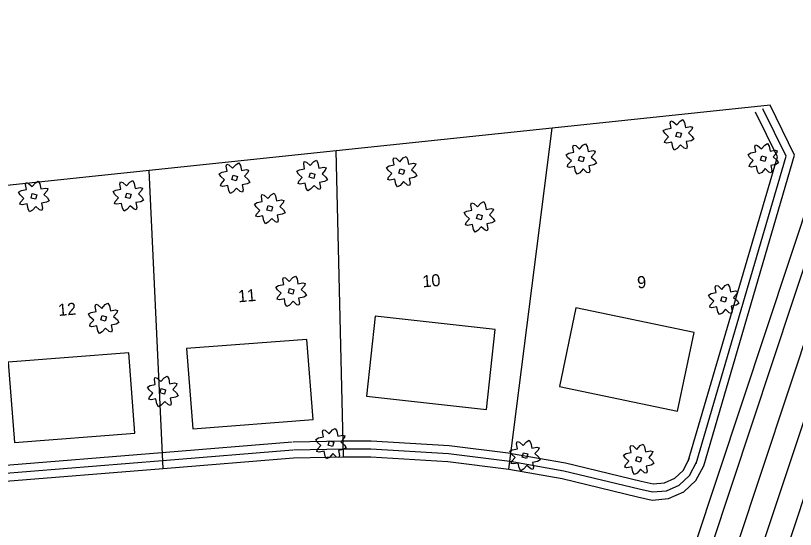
# Model space of a CAD drawing. Extents: x 1810019 to 1811399, y 1074962 to 1076105.
# Drawn here: x 1810548 to 1810935.4, y 1075849.4 to 1076104.6 of the extents above; entities that cross this region are included whole.
import ezdxf

# ---------------------------------------------------------------- set-up
doc = ezdxf.new("R2010")
doc.units = 0
for name, color, linetype in [('Environmental-New trees', 7, 'Continuous'), ('Property-Buildings', 7, 'Continuous'), ('Roadway-Centerline main', 7, 'Continuous'), ('Roadway-Edge of pavement', 7, 'Continuous'), ('Roadway-Edge of shoulder', 7, 'Continuous'), ('Roadway-Land lines', 7, 'Continuous'), ('Roadway-Sidewalks', 7, 'Continuous'), ('Text-Property owner', 7, 'Continuous')]:
    doc.layers.add(name, color=color, linetype=linetype)

msp = doc.modelspace()

# ---------------------------------------------------------------- linework, layer by layer
at = {"layer": 'Environmental-New trees'}
for points in [[(1810870.43, 1076041.5), (1810870.74, 1076042.58), (1810872.43, 1076044.44), (1810870.57, 1076046.14), (1810869.79, 1076047.52), (1810871.14, 1076048.28), (1810873.65, 1076048.77), (1810873.18, 1076051.25), (1810873.48, 1076052.33), (1810874.57, 1076052.02), (1810876.43, 1076050.33), (1810878.12, 1076052.19), (1810879.51, 1076052.97), (1810880.29, 1076051.58), (1810880.76, 1076049.11), (1810883.23, 1076049.58), (1810884.31, 1076049.28), (1810883.94, 1076048.12), (1810882.31, 1076046.33), (1810884.18, 1076044.64), (1810884.95, 1076043.25), (1810883.6, 1076042.49), (1810881.09, 1076042), (1810881.57, 1076039.53), (1810881.26, 1076038.45), (1810880.18, 1076038.75), (1810878.32, 1076040.45), (1810876.62, 1076038.58), (1810875.24, 1076037.81), (1810874.46, 1076039.19), (1810873.99, 1076041.67), (1810871.51, 1076041.19)], [(1810876.59, 1076046.78), (1810878.76, 1076046.17), (1810878.15, 1076044), (1810875.98, 1076044.61)], [(1810822.11, 1076029.49), (1810822.41, 1076030.58), (1810824.1, 1076032.44), (1810822.24, 1076034.13), (1810821.47, 1076035.52), (1810822.82, 1076036.28), (1810825.32, 1076036.77), (1810824.85, 1076039.24), (1810825.16, 1076040.32), (1810826.24, 1076040.02), (1810828.1, 1076038.32), (1810829.79, 1076040.19), (1810831.18, 1076040.96), (1810831.96, 1076039.58), (1810832.43, 1076037.1), (1810834.91, 1076037.58), (1810835.99, 1076037.27), (1810835.62, 1076036.12), (1810833.99, 1076034.33), (1810835.85, 1076032.63), (1810836.63, 1076031.25), (1810835.28, 1076030.49), (1810832.77, 1076029.99), (1810833.24, 1076027.52), (1810832.94, 1076026.44), (1810831.85, 1076026.75), (1810829.99, 1076028.44), (1810828.3, 1076026.58), (1810826.91, 1076025.8), (1810826.13, 1076027.19), (1810825.66, 1076029.66), (1810823.19, 1076029.19)], [(1810912.52, 1076029.64), (1810912.82, 1076030.72), (1810914.51, 1076032.59), (1810912.65, 1076034.28), (1810911.88, 1076035.67), (1810913.23, 1076036.42), (1810915.74, 1076036.92), (1810915.26, 1076039.39), (1810915.57, 1076040.47), (1810916.65, 1076040.17), (1810918.51, 1076038.47), (1810920.21, 1076040.33), (1810921.59, 1076041.11), (1810922.37, 1076039.72), (1810922.84, 1076037.25), (1810925.32, 1076037.73), (1810926.4, 1076037.42), (1810926.03, 1076036.26), (1810924.4, 1076034.48), (1810926.26, 1076032.78), (1810927.04, 1076031.4), (1810925.69, 1076030.64), (1810923.18, 1076030.14), (1810923.65, 1076027.67), (1810923.35, 1076026.59), (1810922.26, 1076026.9), (1810920.4, 1076028.59), (1810918.71, 1076026.73), (1810917.32, 1076025.95), (1810916.54, 1076027.34), (1810916.07, 1076029.81), (1810913.6, 1076029.34)], [(1810688.34, 1076021.25), (1810688.65, 1076022.34), (1810690.34, 1076024.2), (1810688.48, 1076025.89), (1810687.7, 1076027.28), (1810689.05, 1076028.04), (1810691.56, 1076028.53), (1810691.09, 1076031), (1810691.39, 1076032.08), (1810692.48, 1076031.78), (1810694.34, 1076030.09), (1810696.03, 1076031.95), (1810697.42, 1076032.73), (1810698.2, 1076031.34), (1810698.67, 1076028.87), (1810701.14, 1076029.34), (1810702.22, 1076029.03), (1810701.85, 1076027.88), (1810700.22, 1076026.09), (1810702.09, 1076024.4), (1810702.86, 1076023.01), (1810701.51, 1076022.25), (1810699, 1076021.76), (1810699.48, 1076019.29), (1810699.17, 1076018.2), (1810698.09, 1076018.51), (1810696.23, 1076020.2), (1810694.53, 1076018.34), (1810693.15, 1076017.56), (1810692.37, 1076018.95), (1810691.89, 1076021.42), (1810689.42, 1076020.95)], [(1810732.87, 1076023.21), (1810733.17, 1076024.29), (1810734.87, 1076026.16), (1810733.01, 1076027.85), (1810732.23, 1076029.24), (1810733.58, 1076029.99), (1810736.09, 1076030.49), (1810735.61, 1076032.96), (1810735.92, 1076034.04), (1810737, 1076033.74), (1810738.86, 1076032.04), (1810740.56, 1076033.9), (1810741.95, 1076034.68), (1810742.72, 1076033.29), (1810743.2, 1076030.82), (1810745.67, 1076031.3), (1810746.75, 1076030.99), (1810746.38, 1076029.83), (1810744.75, 1076028.05), (1810746.61, 1076026.35), (1810747.39, 1076024.97), (1810746.04, 1076024.21), (1810743.53, 1076023.71), (1810744, 1076021.24), (1810743.7, 1076020.16), (1810742.62, 1076020.46), (1810740.75, 1076022.16), (1810739.06, 1076020.3), (1810737.67, 1076019.52), (1810736.9, 1076020.91), (1810736.42, 1076023.38), (1810733.95, 1076022.91)], [(1810828.27, 1076034.77), (1810830.44, 1076034.16), (1810829.83, 1076031.99), (1810827.66, 1076032.6)], [(1810918.68, 1076034.92), (1810920.85, 1076034.31), (1810920.24, 1076032.14), (1810918.07, 1076032.75)], [(1810649.82, 1076020.02), (1810650.12, 1076021.1), (1810651.82, 1076022.97), (1810649.95, 1076024.66), (1810649.18, 1076026.05), (1810650.53, 1076026.81), (1810653.04, 1076027.3), (1810652.56, 1076029.77), (1810652.87, 1076030.85), (1810653.95, 1076030.55), (1810655.81, 1076028.85), (1810657.51, 1076030.72), (1810658.89, 1076031.49), (1810659.67, 1076030.1), (1810660.14, 1076027.63), (1810662.62, 1076028.11), (1810663.7, 1076027.8), (1810663.33, 1076026.65), (1810661.7, 1076024.86), (1810663.56, 1076023.16), (1810664.34, 1076021.78), (1810662.99, 1076021.02), (1810660.48, 1076020.52), (1810660.95, 1076018.05), (1810660.65, 1076016.97), (1810659.56, 1076017.28), (1810657.7, 1076018.97), (1810656.01, 1076017.11), (1810654.62, 1076016.33), (1810653.84, 1076017.72), (1810653.37, 1076020.19), (1810650.9, 1076019.72)], [(1810655.98, 1076025.3), (1810658.15, 1076024.69), (1810657.54, 1076022.52), (1810655.37, 1076023.13)], [(1810694.5, 1076026.53), (1810696.67, 1076025.92), (1810696.06, 1076023.76), (1810693.89, 1076024.37)], [(1810739.03, 1076028.49), (1810741.2, 1076027.88), (1810740.59, 1076025.71), (1810738.42, 1076026.32)], [(1810550.11, 1076010.89), (1810550.42, 1076011.97), (1810552.11, 1076013.83), (1810550.25, 1076015.53), (1810549.47, 1076016.92), (1810550.82, 1076017.67), (1810553.33, 1076018.17), (1810552.86, 1076020.64), (1810553.16, 1076021.72), (1810554.24, 1076021.42), (1810556.11, 1076019.72), (1810557.8, 1076021.58), (1810559.19, 1076022.36), (1810559.97, 1076020.97), (1810560.44, 1076018.5), (1810562.91, 1076018.97), (1810563.99, 1076018.67), (1810563.62, 1076017.51), (1810561.99, 1076015.72), (1810563.86, 1076014.03), (1810564.63, 1076012.64), (1810563.28, 1076011.89), (1810560.77, 1076011.39), (1810561.25, 1076008.92), (1810560.94, 1076007.84), (1810559.86, 1076008.14), (1810558, 1076009.84), (1810556.3, 1076007.98), (1810554.92, 1076007.2), (1810554.14, 1076008.59), (1810553.66, 1076011.06), (1810551.19, 1076010.58)], [(1810597.07, 1076011.19), (1810597.38, 1076012.28), (1810599.07, 1076014.14), (1810597.21, 1076015.83), (1810596.43, 1076017.22), (1810597.78, 1076017.98), (1810600.29, 1076018.47), (1810599.82, 1076020.94), (1810600.12, 1076022.03), (1810601.21, 1076021.72), (1810603.07, 1076020.03), (1810604.76, 1076021.89), (1810606.15, 1076022.67), (1810606.93, 1076021.28), (1810607.4, 1076018.81), (1810609.87, 1076019.28), (1810610.95, 1076018.97), (1810610.58, 1076017.82), (1810608.96, 1076016.03), (1810610.82, 1076014.34), (1810611.59, 1076012.95), (1810610.24, 1076012.19), (1810607.73, 1076011.7), (1810608.21, 1076009.23), (1810607.9, 1076008.14), (1810606.82, 1076008.45), (1810604.96, 1076010.14), (1810603.26, 1076008.28), (1810601.88, 1076007.5), (1810601.1, 1076008.89), (1810600.63, 1076011.36), (1810598.15, 1076010.89)], [(1810556.27, 1076016.17), (1810558.44, 1076015.56), (1810557.83, 1076013.39), (1810555.66, 1076014)], [(1810603.23, 1076016.47), (1810605.4, 1076015.86), (1810604.79, 1076013.7), (1810602.62, 1076014.31)], [(1810667.31, 1076004.94), (1810667.62, 1076006.02), (1810669.31, 1076007.88), (1810667.45, 1076009.58), (1810666.67, 1076010.97), (1810668.03, 1076011.72), (1810670.53, 1076012.22), (1810670.06, 1076014.69), (1810670.37, 1076015.77), (1810671.45, 1076015.47), (1810673.31, 1076013.77), (1810675, 1076015.63), (1810676.39, 1076016.41), (1810677.17, 1076015.02), (1810677.64, 1076012.55), (1810680.11, 1076013.02), (1810681.2, 1076012.72), (1810680.83, 1076011.56), (1810679.2, 1076009.78), (1810681.06, 1076008.08), (1810681.84, 1076006.69), (1810680.48, 1076005.94), (1810677.98, 1076005.44), (1810678.45, 1076002.97), (1810678.14, 1076001.89), (1810677.06, 1076002.19), (1810675.2, 1076003.89), (1810673.51, 1076002.03), (1810672.12, 1076001.25), (1810671.34, 1076002.64), (1810670.87, 1076005.11), (1810668.4, 1076004.64)], [(1810673.48, 1076010.22), (1810675.64, 1076009.61), (1810675.03, 1076007.44), (1810672.87, 1076008.05)], [(1810771.48, 1076000.73), (1810771.78, 1076001.81), (1810773.48, 1076003.68), (1810771.61, 1076005.37), (1810770.84, 1076006.76), (1810772.19, 1076007.52), (1810774.7, 1076008.01), (1810774.22, 1076010.48), (1810774.53, 1076011.56), (1810775.61, 1076011.26), (1810777.47, 1076009.56), (1810779.17, 1076011.43), (1810780.55, 1076012.2), (1810781.33, 1076010.81), (1810781.8, 1076008.34), (1810784.28, 1076008.82), (1810785.36, 1076008.51), (1810784.99, 1076007.35), (1810783.36, 1076005.57), (1810785.22, 1076003.87), (1810786, 1076002.49), (1810784.65, 1076001.73), (1810782.14, 1076001.23), (1810782.61, 1075998.76), (1810782.31, 1075997.68), (1810781.22, 1075997.99), (1810779.36, 1075999.68), (1810777.67, 1075997.82), (1810776.28, 1075997.04), (1810775.5, 1075998.43), (1810775.03, 1076000.9), (1810772.56, 1076000.43)], [(1810777.64, 1076006.01), (1810779.81, 1076005.4), (1810779.2, 1076003.23), (1810777.03, 1076003.84)], [(1810677.94, 1075963.76), (1810678.25, 1075964.84), (1810679.94, 1075966.7), (1810678.08, 1075968.39), (1810677.3, 1075969.78), (1810678.65, 1075970.54), (1810681.16, 1075971.03), (1810680.69, 1075973.5), (1810680.99, 1075974.59), (1810682.07, 1075974.28), (1810683.94, 1075972.59), (1810685.63, 1075974.45), (1810687.02, 1075975.23), (1810687.8, 1075973.84), (1810688.27, 1075971.37), (1810690.74, 1075971.84), (1810691.82, 1075971.54), (1810691.45, 1075970.38), (1810689.82, 1075968.59), (1810691.69, 1075966.9), (1810692.46, 1075965.51), (1810691.11, 1075964.75), (1810688.6, 1075964.26), (1810689.08, 1075961.79), (1810688.77, 1075960.7), (1810687.69, 1075961.01), (1810685.83, 1075962.7), (1810684.13, 1075960.84), (1810682.75, 1075960.06), (1810681.97, 1075961.45), (1810681.49, 1075963.92), (1810679.02, 1075963.45)], [(1810892.83, 1075959.77), (1810893.14, 1075960.86), (1810894.83, 1075962.72), (1810892.97, 1075964.41), (1810892.19, 1075965.8), (1810893.54, 1075966.56), (1810896.05, 1075967.05), (1810895.58, 1075969.52), (1810895.88, 1075970.6), (1810896.97, 1075970.3), (1810898.83, 1075968.61), (1810900.52, 1075970.47), (1810901.91, 1075971.24), (1810902.69, 1075969.86), (1810903.16, 1075967.39), (1810905.63, 1075967.86), (1810906.71, 1075967.55), (1810906.35, 1075966.4), (1810904.72, 1075964.61), (1810906.58, 1075962.92), (1810907.35, 1075961.53), (1810906, 1075960.77), (1810903.5, 1075960.28), (1810903.97, 1075957.81), (1810903.66, 1075956.72), (1810902.58, 1075957.03), (1810900.72, 1075958.72), (1810899.03, 1075956.86), (1810897.64, 1075956.08), (1810896.86, 1075957.47), (1810896.39, 1075959.94), (1810893.91, 1075959.47)], [(1810684.1, 1075969.03), (1810686.27, 1075968.42), (1810685.66, 1075966.26), (1810683.49, 1075966.87)], [(1810898.99, 1075965.05), (1810901.16, 1075964.44), (1810900.55, 1075962.27), (1810898.38, 1075962.89)], [(1810584.77, 1075950.37), (1810585.07, 1075951.45), (1810586.76, 1075953.31), (1810584.9, 1075955), (1810584.13, 1075956.39), (1810585.48, 1075957.15), (1810587.99, 1075957.64), (1810587.51, 1075960.11), (1810587.82, 1075961.2), (1810588.9, 1075960.89), (1810590.76, 1075959.2), (1810592.46, 1075961.06), (1810593.84, 1075961.84), (1810594.62, 1075960.45), (1810595.09, 1075957.98), (1810597.57, 1075958.45), (1810598.65, 1075958.15), (1810598.28, 1075956.99), (1810596.65, 1075955.2), (1810598.51, 1075953.51), (1810599.29, 1075952.12), (1810597.94, 1075951.36), (1810595.43, 1075950.87), (1810595.9, 1075948.4), (1810595.6, 1075947.31), (1810594.51, 1075947.62), (1810592.65, 1075949.31), (1810590.96, 1075947.45), (1810589.57, 1075946.67), (1810588.79, 1075948.06), (1810588.32, 1075950.53), (1810585.85, 1075950.06)], [(1810590.93, 1075955.64), (1810593.1, 1075955.03), (1810592.49, 1075952.87), (1810590.32, 1075953.48)], [(1810614.16, 1075914.05), (1810614.47, 1075915.13), (1810616.16, 1075916.99), (1810614.3, 1075918.68), (1810613.52, 1075920.07), (1810614.87, 1075920.83), (1810617.38, 1075921.32), (1810616.91, 1075923.79), (1810617.21, 1075924.88), (1810618.29, 1075924.57), (1810620.16, 1075922.88), (1810621.85, 1075924.74), (1810623.24, 1075925.52), (1810624.02, 1075924.13), (1810624.49, 1075921.66), (1810626.96, 1075922.13), (1810628.04, 1075921.83), (1810627.67, 1075920.67), (1810626.04, 1075918.88), (1810627.91, 1075917.19), (1810628.68, 1075915.8), (1810627.33, 1075915.04), (1810624.82, 1075914.55), (1810625.3, 1075912.08), (1810624.99, 1075910.99), (1810623.91, 1075911.3), (1810622.05, 1075912.99), (1810620.35, 1075911.13), (1810618.97, 1075910.35), (1810618.19, 1075911.74), (1810617.71, 1075914.21), (1810615.24, 1075913.74)], [(1810620.32, 1075919.32), (1810622.49, 1075918.71), (1810621.88, 1075916.55), (1810619.71, 1075917.16)], [(1810697.7, 1075888.09), (1810698, 1075889.18), (1810699.7, 1075891.04), (1810697.84, 1075892.73), (1810697.06, 1075894.12), (1810698.41, 1075894.88), (1810700.92, 1075895.37), (1810700.45, 1075897.84), (1810700.75, 1075898.92), (1810701.83, 1075898.62), (1810703.7, 1075896.93), (1810705.39, 1075898.79), (1810706.78, 1075899.56), (1810707.55, 1075898.18), (1810708.03, 1075895.71), (1810710.5, 1075896.18), (1810711.58, 1075895.87), (1810711.21, 1075894.72), (1810709.58, 1075892.93), (1810711.44, 1075891.24), (1810712.22, 1075889.85), (1810710.87, 1075889.09), (1810708.36, 1075888.6), (1810708.84, 1075886.12), (1810708.53, 1075885.04), (1810707.45, 1075885.35), (1810705.59, 1075887.04), (1810703.89, 1075885.18), (1810702.5, 1075884.4), (1810701.73, 1075885.79), (1810701.25, 1075888.26), (1810698.78, 1075887.79)], [(1810703.86, 1075893.37), (1810706.03, 1075892.76), (1810705.42, 1075890.59), (1810703.25, 1075891.2)], [(1810794.14, 1075882.19), (1810794.44, 1075883.28), (1810796.14, 1075885.14), (1810794.28, 1075886.83), (1810793.5, 1075888.22), (1810794.85, 1075888.98), (1810797.36, 1075889.47), (1810796.88, 1075891.94), (1810797.19, 1075893.02), (1810798.27, 1075892.72), (1810800.13, 1075891.03), (1810801.83, 1075892.89), (1810803.21, 1075893.66), (1810803.99, 1075892.28), (1810804.47, 1075889.81), (1810806.94, 1075890.28), (1810808.02, 1075889.97), (1810807.65, 1075888.82), (1810806.02, 1075887.03), (1810807.88, 1075885.34), (1810808.66, 1075883.95), (1810807.31, 1075883.19), (1810804.8, 1075882.7), (1810805.27, 1075880.23), (1810804.97, 1075879.14), (1810803.89, 1075879.45), (1810802.02, 1075881.14), (1810800.33, 1075879.28), (1810798.94, 1075878.5), (1810798.16, 1075879.89), (1810797.69, 1075882.36), (1810795.22, 1075881.89)], [(1810850.63, 1075880.3), (1810850.93, 1075881.38), (1810852.63, 1075883.24), (1810850.76, 1075884.94), (1810849.99, 1075886.32), (1810851.34, 1075887.08), (1810853.85, 1075887.57), (1810853.37, 1075890.05), (1810853.68, 1075891.13), (1810854.76, 1075890.82), (1810856.62, 1075889.13), (1810858.32, 1075890.99), (1810859.7, 1075891.77), (1810860.48, 1075890.38), (1810860.96, 1075887.91), (1810863.43, 1075888.38), (1810864.51, 1075888.08), (1810864.14, 1075886.92), (1810862.51, 1075885.13), (1810864.37, 1075883.44), (1810865.15, 1075882.05), (1810863.8, 1075881.29), (1810861.29, 1075880.8), (1810861.76, 1075878.33), (1810861.46, 1075877.25), (1810860.37, 1075877.55), (1810858.51, 1075879.24), (1810856.82, 1075877.38), (1810855.43, 1075876.61), (1810854.65, 1075877.99), (1810854.18, 1075880.47), (1810851.71, 1075879.99)], [(1810800.3, 1075887.47), (1810802.47, 1075886.86), (1810801.86, 1075884.69), (1810799.69, 1075885.31)], [(1810856.79, 1075885.58), (1810858.96, 1075884.97), (1810858.35, 1075882.8), (1810856.18, 1075883.41)]]:
    msp.add_lwpolyline(points, close=True, dxfattribs=at)
at = {"layer": 'Property-Buildings'}
for points in [[(1810876.91, 1075908.04), (1810885.08, 1075947.2), (1810826.35, 1075959.46), (1810818.18, 1075920.3)], [(1810781.88, 1075908.93), (1810786.31, 1075948.69), (1810726.68, 1075955.33), (1810722.25, 1075915.58)], [(1810695.77, 1075903.91), (1810692.73, 1075943.79), (1810632.91, 1075939.24), (1810635.94, 1075899.36)], [(1810607.18, 1075897.17), (1810604.15, 1075937.05), (1810544.32, 1075932.5), (1810547.35, 1075892.62)]]:
    msp.add_lwpolyline(points, close=True, dxfattribs=at)
at = {"layer": 'Roadway-Centerline main'}
msp.add_line((1811006.18, 1076104.35), (1810632.15, 1074976.37), dxfattribs=at)
at = {"layer": 'Roadway-Edge of pavement'}
for p, q in [((1810980.71, 1076103.81), (1810606.02, 1074973.81)), ((1810993.45, 1076104.08), (1810619.08, 1074975.09)), ((1811018.91, 1076104.62), (1810645.22, 1074977.65))]:
    msp.add_line(p, q, dxfattribs=at)
at = {"layer": 'Roadway-Edge of shoulder'}
msp.add_line((1810972.23, 1076103.63), (1810597.31, 1074972.96), dxfattribs=at)
at = {"layer": 'Roadway-Land lines'}
for p, q in [((1810922.82, 1076060.14), (1810814.61, 1076048.76)), ((1810935.04, 1076035.22), (1810922.82, 1076060.14)), ((1810814.61, 1076048.76), (1810707.16, 1076037.46)), ((1810792.99, 1075879.26), (1810814.61, 1076048.76)), ((1810707.16, 1076037.46), (1810614.28, 1076027.7)), ((1810710.95, 1075885.45), (1810707.16, 1076037.46)), ((1810889.89, 1075880.99), (1810935.04, 1076035.22)), ((1810614.28, 1076027.7), (1810525.87, 1076018.4)), ((1810621.22, 1075879.66), (1810614.28, 1076027.7)), ((1810621.22, 1075879.66), (1810686.04, 1075884.93)), ((1810535.19, 1075872.66), (1810621.22, 1075879.66))]:
    msp.add_line(p, q, dxfattribs=at)
for points in [[(1810686.04, 1075884.93), (1810710.95, 1075885.45)], [(1810710.95, 1075885.45), (1810724.4, 1075885.37), (1810762.7, 1075883.09), (1810792.99, 1075879.26)], [(1810792.99, 1075879.26), (1810819.61, 1075874.62), (1810856.91, 1075865.64)], [(1810856.91, 1075865.64), (1810864.17, 1075863.95), (1810872.41, 1075864.67), (1810879.96, 1075868.04), (1810886.01, 1075873.68), (1810889.89, 1075880.99)]]:
    msp.add_lwpolyline(points, dxfattribs=at)
at = {"layer": 'Roadway-Sidewalks'}
for p, q in [((1810926.49, 1076034.49), (1810915.64, 1076056.62)), ((1810930.77, 1076034.86), (1810919.23, 1076058.38)), ((1810882.21, 1075883.23), (1810926.49, 1076034.49)), ((1810886.05, 1075882.11), (1810930.77, 1076034.86)), ((1810620.57, 1075887.63), (1810685.39, 1075892.91)), ((1810534.54, 1075880.63), (1810620.57, 1075887.63)), ((1810620.89, 1075883.65), (1810685.71, 1075888.92)), ((1810534.86, 1075876.64), (1810620.89, 1075883.65))]:
    msp.add_line(p, q, dxfattribs=at)
for points in [[(1810685.87, 1075892.93), (1810710.79, 1075893.45)], [(1810711, 1075893.45), (1810724.67, 1075893.36), (1810763.44, 1075891.06), (1810794, 1075887.2)], [(1810685.96, 1075888.93), (1810710.87, 1075889.45)], [(1810710.98, 1075889.45), (1810724.53, 1075889.37), (1810763.07, 1075887.07), (1810793.5, 1075883.23)], [(1810794.37, 1075887.15), (1810821.23, 1075882.45), (1810858.78, 1075873.42)], [(1810793.68, 1075883.21), (1810820.42, 1075878.54), (1810857.85, 1075869.53)], [(1810857.82, 1075869.54), (1810864.45, 1075867.99), (1810871.39, 1075868.6), (1810877.73, 1075871.42), (1810882.79, 1075876.15), (1810886.35, 1075882.86)], [(1810858.72, 1075873.43), (1810864.74, 1075872.03), (1810870.38, 1075872.52), (1810875.49, 1075874.8), (1810879.57, 1075878.61), (1810882.82, 1075884.73)]]:
    msp.add_lwpolyline(points, dxfattribs=at)

# ---------------------------------------------------------------- texts
at = {"layer": 'Text-Property owner'}
for s, p in [('10', (1810750.35, 1075969.61)), ('9', (1810857.05, 1075969.07)), ('11', (1810658.69, 1075962.17)), ('12', (1810569.35, 1075955.39))]:
    msp.add_text(s, height=6, rotation=4.6517, dxfattribs=at).set_placement(p)

doc.saveas('drawing.dxf')
